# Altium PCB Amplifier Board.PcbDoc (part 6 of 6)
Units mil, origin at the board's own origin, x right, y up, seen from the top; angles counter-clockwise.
Board outline 6000 x 2640 mil, 6 copper layers (Top Layer, GND, VCC, BASES, GND (Plane3), Bottom Layer), stack 63.9 mil thick; 884 components, 484 nets, 2029 pads, 464 vias.
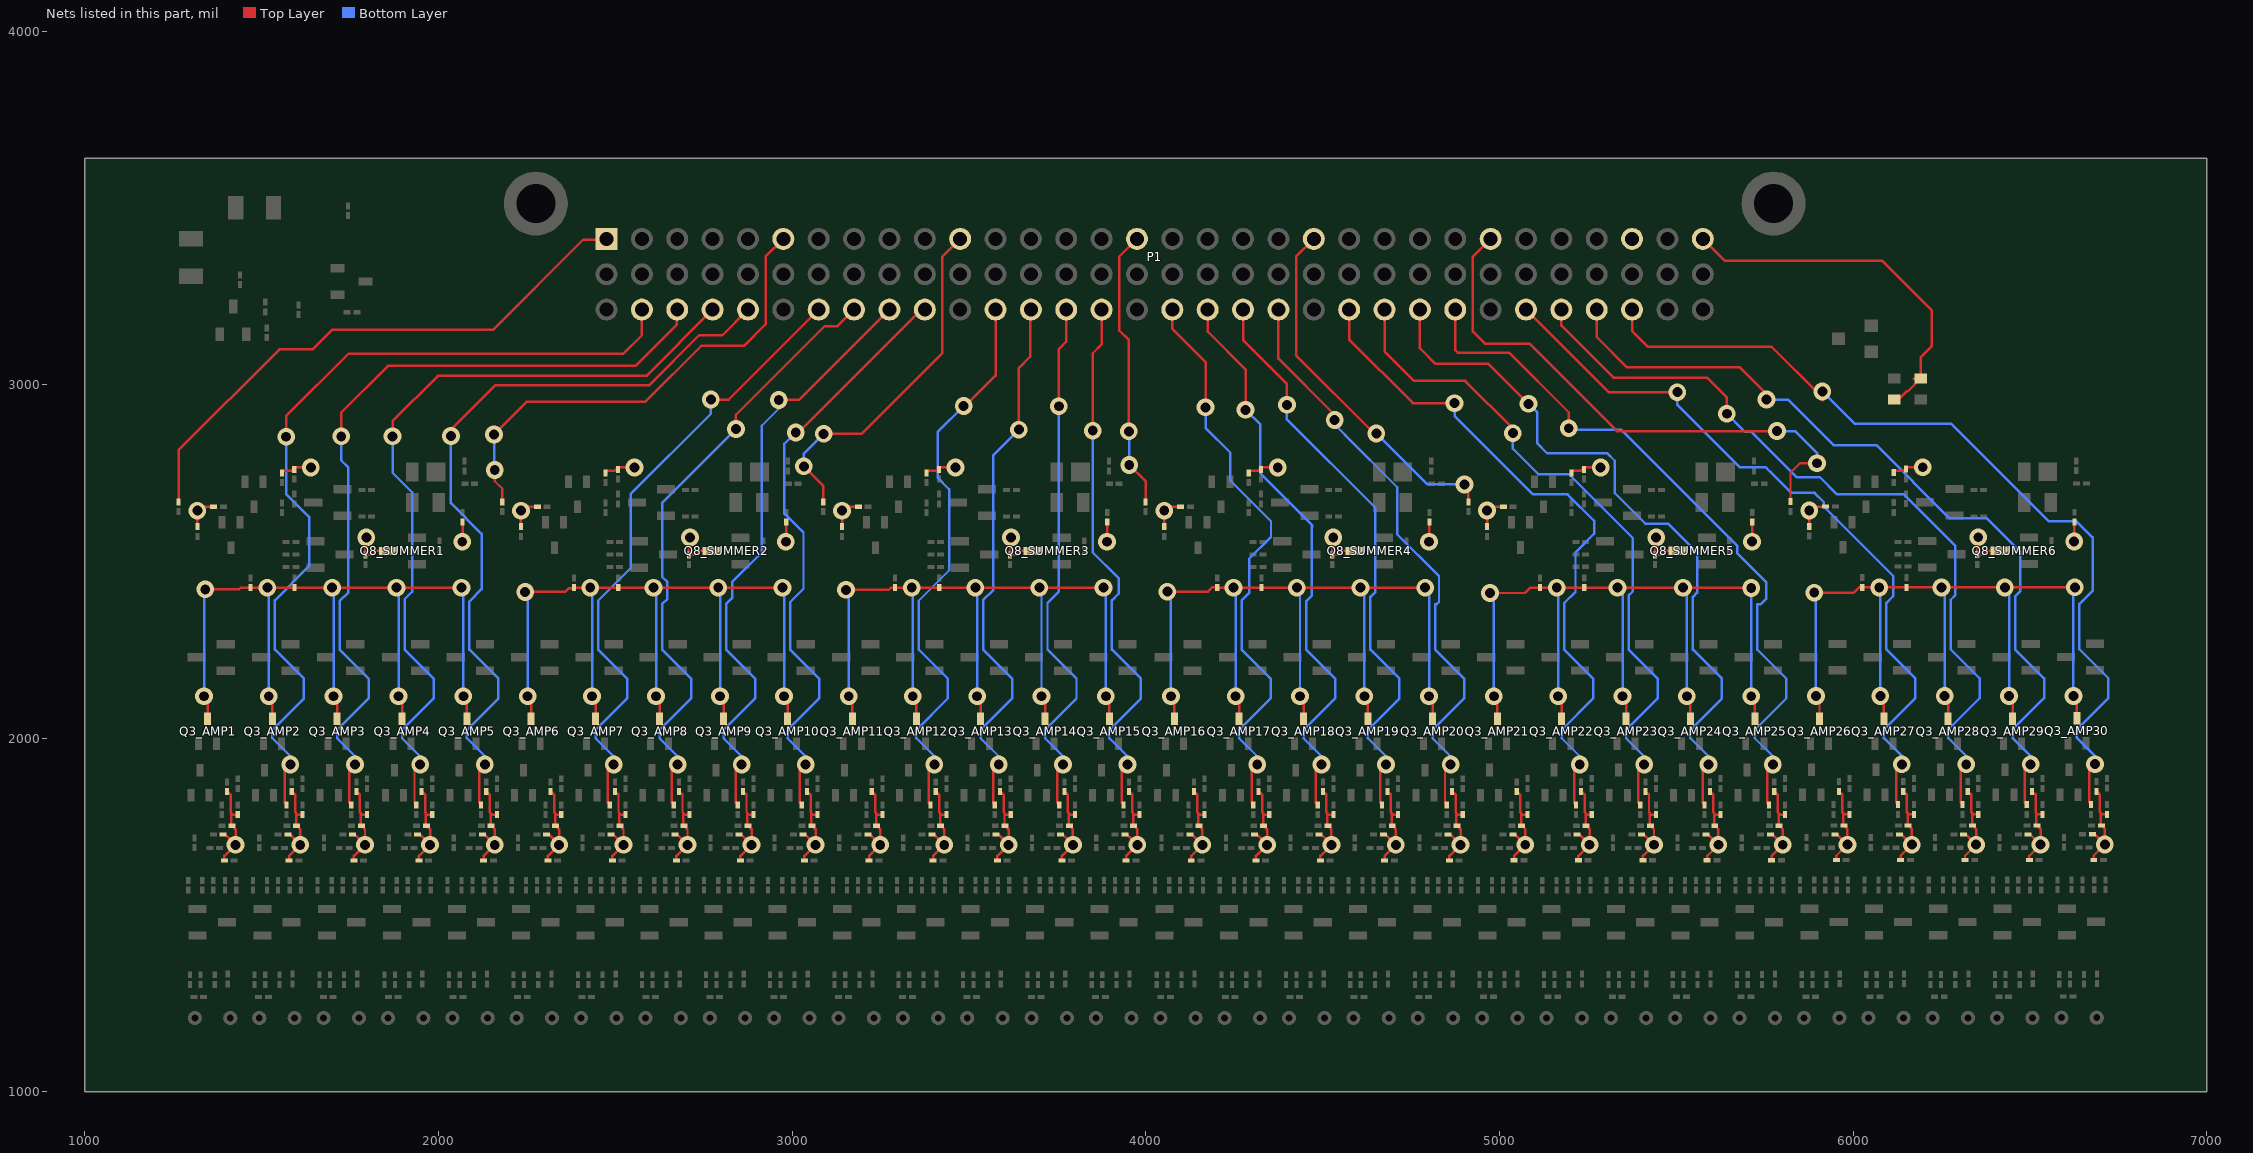
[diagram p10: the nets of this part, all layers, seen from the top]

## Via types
v1: diameter 50, hole 28, Top Layer to Bottom Layer, 433 vias
v2: diameter 50, hole 28, Top Layer to Bottom Layer, tented top, 31 vias

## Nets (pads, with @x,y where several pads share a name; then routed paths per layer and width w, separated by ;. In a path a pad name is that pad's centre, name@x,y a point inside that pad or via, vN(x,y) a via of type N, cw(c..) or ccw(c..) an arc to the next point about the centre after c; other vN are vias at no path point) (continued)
SIPMOUT2_SUMMER1: C5_AMP2.2 P1.C2 | length 2433.2
  Top Layer w7: C5_AMP2.2@1565.78,1817 1565,1817.78 1565,1910 v1(1581,1926) ; v1(1569,2853) 1569,2911 1746,3088 2523,3088 2575,3140 P1.C2@2575,3212.36
  Bottom Layer w7: v1(1569,2853) 1569,2691 1634,2626 1634,2487.16 1537,2390.16 1537,2251 1619,2169 1619,2113 1530,2024 1530,2000.32 1581,1949.32 v1(1581,1926)
SIPMOUT2_SUMMER2: C5_AMP7.2 P1.C7 | length 1782.4
  Top Layer w7: C5_AMP7.2@2479.78,1817 2479,1817.78 2479,1910 v1(2495,1926) ; v1(2770,2958) 2820.64,2958 P1.C7@3075,3212.36
  Bottom Layer w7: v1(2495,1926) 2495,1949.32 2444,2000.32 2444,2024 2533,2113 2533,2169 2451,2251 2451,2389 2543,2481 2543,2691 2770,2918 v1(2770,2958)
SIPMOUT2_SUMMER3: C5_AMP12.2 P1.C12 | length 1613.8
  Top Layer w7: C5_AMP12.2@3386.78,1817 3386,1817.78 3386,1910 v1(3402,1926) ; v1(3485,2940) 3489,2940 3575,3026 P1.C12@3575,3212.36
  Bottom Layer w7: v1(3402,1926) 3402,1949.32 3351,2000.32 3351,2024 3440,2113 3440,2169 3358,2251 3358,2389.22 3444,2475.22 3444,2704.16 3411,2737.16 3411,2866 v1(3485,2940)
SIPMOUT2_SUMMER4: C5_AMP17.2 P1.C17 | length 1644.2
  Top Layer w7: P1.C17@4075,3212.36 4075,3158 4169,3064 v1(4169,2936) ; C5_AMP17.2@4299.78,1817 4299,1817.78 4299,1910 v1(4315,1926)
  Bottom Layer w7: v1(4169,2936) 4169,2878 4238.84,2808.16 4238.84,2729 4354,2613.84 4354,2569.77 4292,2507.77 4292,2410.5 4271,2389.5 4271,2251 4353,2169 4353,2113 4264,2024 4264,2000.32 4315,1949.32 v1(4315,1926)
SIPMOUT2_SUMMER5: C5_AMP22.2 P1.C22 | length 1943
  Top Layer w7: P1.C22@4575,3212.36 4575,3128 4755,2948 v1(4873,2948) ; C5_AMP22.2@5211.78,1817.1 5211,1817.88 5211,1910.1 v1(5227,1926.1)
  Bottom Layer w7: v1(4873,2948) 4873,2911.7 5094.6,2690.1 5192.74,2690.1 5268,2614.84 5268,2579 5215,2526 5215,2414 5183,2382 5183,2251.1 5265,2169.1 5265,2113.1 5176,2024.1 5176,2000.42 5227,1949.42 v1(5227,1926.1)
SIPMOUT2_SUMMER6: C5_AMP27.2 P1.C27 | length 2125.1
  Top Layer w7: P1.C27@5075,3212.36 5308.36,2979 v1(5503,2979) ; C5_AMP27.2@6122.78,1817.57 6122,1818.35 6122,1910.57 v1(6138,1926.57)
  Bottom Layer w7: v1(5503,2979) 5503,2943 5679,2767 5752,2767 5765.59,2753.41 5766.59,2753.41 5823,2697 ; 5824,2694 5891,2694 5917,2668 5917,2655.57 6113.44,2459.13 6113.44,2402.44 6094,2383 6094,2251.57 6176,2169.57 6176,2113.57 6087,2024.57 6087,2000.89 6138,1949.89 v1(6138,1926.57)
SIPMOUT3_SUMMER1: C5_AMP3.2 P1.C3 | length 2313.6
  Top Layer w7: v1(1725,2854) 1725,2921 1857,3053 2557,3053 2673,3169 P1.C3@2673,3210.36 ; C5_AMP3.2@1748.78,1817 1748,1817.78 1748,1910 v1(1764,1926)
  Bottom Layer w7: v1(1725,2854) 1725,2786 1745,2766 1745,2413 1720,2388 1720,2251 1802,2169 1802,2113 1713,2024 1713,2000.32 1764,1949.32 v1(1764,1926)
SIPMOUT3_SUMMER2: C5_AMP8.2 P1.C8 | length 1753.1
  Top Layer w7: C5_AMP8.2@2660.78,1817 2660,1817.78 2660,1910 v1(2676,1926) ; v1(2841,2875) 2841,2915 3092,3166 3128.64,3166 P1.C8@3175,3212.36
  Bottom Layer w7: v1(2676,1926) 2676,1949.32 2625,2000.32 2625,2024 2714,2113 2714,2169 2632,2251 2632,2379.43 2647,2394.43 2647,2442 2632,2457 2632,2666 v1(2841,2875)
SIPMOUT3_SUMMER3: C5_AMP13.2 P1.C13 | length 1547.4
  Top Layer w7: C5_AMP13.2@3568.78,1817 3568,1817.78 3568,1910 v1(3584,1926) ; v1(3641,2873) 3641,3047 3673,3079 P1.C13@3673,3210.36
  Bottom Layer w7: v1(3584,1926) 3584,1949.32 3533,2000.32 3533,2024 3622,2113 3622,2169 3540,2251 3540,2391 3569,2420 3569,2801 v1(3641,2873)
SIPMOUT3_SUMMER4: C5_AMP18.2 P1.C18 | length 1624.3
  Top Layer w7: P1.C18@4175,3212.36 4175,3150 4282,3043 v1(4282,2929) ; C5_AMP18.2@4481.78,1817 4481,1817.78 4481,1910 v1(4497,1926)
  Bottom Layer w7: v1(4282,2929) 4324,2887 4324,2749.23 4470,2603.23 4470,2598.1 ; 4469,2599.32 4469,2403 4453,2387 4453,2251 4535,2169 4535,2113 4446,2024 4446,2000.32 4497,1949.32 v1(4497,1926)
SIPMOUT3_SUMMER5: C5_AMP23.2 P1.C23 | length 1925.2
  Top Layer w7: P1.C23@4675,3212.36 4675,3094 4758,3011 4903,3011 5038,2876 v1(5038,2863) ; C5_AMP23.2@5393.78,1817.1 5393,1817.88 5393,1910.1 v1(5409,1926.1)
  Bottom Layer w7: v1(5038,2863) 5038,2819 5109.81,2747.19 5195.81,2747.19 5377,2566 5377,2415.49 5365,2403.49 5365,2251.1 5447,2169.1 5447,2113.1 5358,2024.1 5358,2000.42 5409,1949.42 v1(5409,1926.1)
SIPMOUT3_SUMMER6: C5_AMP28.2 P1.C28 | length 2275.4
  Top Layer w7: P1.C28@5175,3212.36 5175,3167 5322,3020 5587,3020 5643,2964 v1(5643,2918) ; C5_AMP28.2@6304.78,1817.57 6304,1818.35 6304,1910.57 v1(6320,1926.57)
  Bottom Layer w7: v1(5643,2918) 5692,2869 5710.4,2869 5840.4,2739 5905.7,2739 5954.73,2689.97 6143.5,2689.97 6289,2544.48 6289,2405 6276,2392 6276,2251.57 6358,2169.57 6358,2113.57 6269,2024.57 6269,2000.89 6320,1949.89 v1(6320,1926.57)
SIPMOUT4_SUMMER1: C5_AMP4.2 P1.C4 | length 2246.5
  Top Layer w7: v1(1870,2854) 1870,2897 1998,3025 2587.64,3025 P1.C4@2775,3212.36 ; C5_AMP4.2@1932.78,1817 1932,1817.78 1932,1910 v1(1948,1926)
  Bottom Layer w7: v1(1870,2854) 1870,2751 1925.56,2695.44 1925.56,2414.78 1904,2393.22 1904,2251 1986,2169 1986,2113 1897,2024 1897,2000.32 1948,1949.32 v1(1948,1926)
SIPMOUT4_SUMMER2: C5_AMP9.2 P1.C9 | length 1719.4
  Top Layer w7: C5_AMP9.2@2841.78,1817 2841,1817.78 2841,1910 v1(2857,1926) ; v1(2962,2957) 3019.64,2957 P1.C9@3275,3212.36
  Bottom Layer w7: v1(2857,1926) 2857,1949.32 2806,2000.32 2806,2024 2895,2113 2895,2169 2813,2251 2813,2379.43 2830,2396.43 2830,2442 2914,2526 2914,2884 2962,2932 v1(2962,2957)
SIPMOUT4_SUMMER3: C5_AMP14.2 P1.C14 | length 1516.2
  Top Layer w7: C5_AMP14.2@3750.78,1817 3750,1817.78 3750,1910 v1(3766,1926) ; v1(3754,2939) 3754,3101 3775,3122 P1.C14@3775,3212.36
  Bottom Layer w7: v1(3754,2939) 3754,2415 3722,2383 3722,2251 3804,2169 3804,2113 3715,2024 3715,2000.32 3766,1949.32 v1(3766,1926)
SIPMOUT4_SUMMER4: C5_AMP19.2 P1.C19 | length 1655
  Top Layer w7: P1.C19@4275,3212.36 4275,3126 4399,3002 v1(4399,2943) ; C5_AMP19.2@4663.78,1817 4663,1817.78 4663,1910 v1(4679,1926)
  Bottom Layer w7: v1(4399,2943) 4399,2902 4649,2652 4649,2413.8 4635,2399.8 4635,2251 4717,2169 4717,2113 4628,2024 4628,2000.32 4679,1949.32 v1(4679,1926)
SIPMOUT4_SUMMER5: C5_AMP24.2 P1.C24 | length 2049.2
  Top Layer w7: P1.C24@4775,3212.36 4775,3103 4819,3059 4969,3059 v1(5082,2946) ; C5_AMP24.2@5575.78,1817.1 5575,1817.88 5575,1910.1 v1(5591,1926.1)
  Bottom Layer w7: v1(5082,2946) 5107,2921 5107,2834 5135,2806 5305,2806 5326,2785 5326,2693.44 5412.34,2607.1 5477,2607.1 5559,2525.1 5559,2411.9 5547,2399.9 5547,2251.1 5629,2169.1 5629,2113.1 5540,2024.1 5540,2000.42 5591,1949.42 v1(5591,1926.1)
SIPMOUT4_SUMMER6: C5_AMP29.2 P1.C29 | length 2351.3
  Top Layer w7: P1.C29@5275,3212.36 5275,3135 5361,3049 5680,3049 5755,2974 v1(5755,2958) ; C5_AMP29.2@6486.78,1817.57 6486,1818.35 6486,1910.57 v1(6502,1926.57)
  Bottom Layer w7: v1(5755,2958) 5816,2958 5945,2829 6065.7,2829 6272.7,2622 6378.29,2622 6473,2527.29 6473,2416.47 6458,2401.47 6458,2251.57 6540,2169.57 6540,2113.57 6451,2024.57 6451,2000.89 6502,1949.89 v1(6502,1926.57)
SIPMOUT5_SUMMER1: C5_AMP5.2 P1.C5 | length 2186
  Top Layer w7: v1(2035,2855) 2035,2873 2160,2998 2595,2998 2737,3140 2802.64,3140 P1.C5@2875,3212.36 ; C5_AMP5.2@2115.78,1817 2115,1817.78 2115,1910 v1(2131,1926)
  Bottom Layer w7: v1(2035,2855) 2035,2665 2122,2578 2122,2422 2087,2387 2087,2251 2169,2169 2169,2113 2080,2024 2080,2000.32 2131,1949.32 v1(2131,1926)
SIPMOUT5_SUMMER2: C5_AMP10.2 P1.C10 | length 1697.4
  Top Layer w7: v1(3010,2865) 3018,2865 P1.C10@3365.36,3212.36 ; C5_AMP10.2@3022.78,1817 3022,1817.78 3022,1910 v1(3038,1926)
  Bottom Layer w7: v1(3010,2865) 2978.16,2833.16 2978.16,2635.75 3032,2581.91 3032,2423 2994,2385 2994,2251 3076,2169 3076,2113 2987,2024 2987,2000.32 3038,1949.32 v1(3038,1926)
SIPMOUT5_SUMMER3: C5_AMP15.2 P1.C15 | length 1542.7
  Top Layer w7: v1@3850,2873 3850,3089 3875,3114 P1.C15@3875,3212.36 ; C5_AMP15.2@3932.78,1817 3932,1817.78 3932,1910 v1(3948,1926)
  Bottom Layer w7: v1@3850,2873 v1(3850,2870) 3850,2526 3923,2453 3923,2409 3904,2390 3904,2251 3986,2169 3986,2113 3897,2024 3897,2000.32 3948,1949.32 v1(3948,1926)
SIPMOUT5_SUMMER4: C5_AMP20.2 P1.C20 | length 1686
  Top Layer w7: P1.C20@4375,3212.36 4375,3074 4534,2915 v1(4534,2900) ; C5_AMP20.2@4846.78,1817 4846,1817.78 4846,1910 v1(4862,1926)
  Bottom Layer w7: v1@4528,2894 4562,2860 4562,2859 4711,2710 4711,2576.91 4829,2458.91 4829,2386 4822.43,2379.43 4818,2379.43 4818,2251 4900,2169 4900,2113 4811,2024 4811,2000.32 4862,1949.32 v1(4862,1926)
SIPMOUT5_SUMMER5: C5_AMP25.2 P1.C25 | length 2044.9
  Top Layer w7: P1.C25@4875,3212.36 4875,3098 4882,3091 5027,3091 5196,2922 v1(5196,2877) ; C5_AMP25.2@5757.78,1817.1 5757,1817.88 5757,1910.1 v1(5773,1926.1)
  Bottom Layer w7: v1(5196,2877) 5201,2872 5345,2872 5672,2545 5672,2524 5755,2441 5755,2395 5739.53,2379.53 5729,2379.53 5729,2251.1 5811,2169.1 5811,2113.1 5722,2024.1 5722,2000.42 5773,1949.42 v1(5773,1926.1)
SIPMOUT5_SUMMER6: C5_AMP30.2 P1.C30 | length 2484.4
  Top Layer w7: P1.C30@5375,3212.36 5375,3152 5420,3107 5770,3107 5904.5,2972.5 5914,2963 5914,2956 ; C5_AMP30.2@6668.78,1818 6668,1818.78 6668,1911 v1(6684,1927)
  Bottom Layer w7: v1(5913,2981) 6005,2889 6278,2889 6553.43,2613.57 6631.5,2613.57 6677,2568.07 6677,2417 6640,2380 ; 6640,2380.43 6640,2380 ; v1(6684,1927) 6684,1950.32 6633,2001.32 6633,2025 6722,2114 6722,2170 6640,2252 6640,2380
SUMMEDOUT1: C9_SUMMER1.2 P1.A1 | length 1603.7
  Top Layer w7: C9_SUMMER1.2@1265,2668.78 1265,2815 1550,3100 1644,3100 1699,3155 2154,3155 2409,3410 2472.64,3410 P1.A1@2475,3412.36
SUMMEDOUT2: C9_SUMMER2.2 P1.A6 | length 1356.2
  Top Layer w7: v1(2157,2859) 2250,2952 2585,2952 2743,3110 2864,3110 2925,3171 2925,3362.36 P1.A6@2975,3412.36 ; v1(2159,2759) 2159,2727 2180,2706 C9_SUMMER2.2@2180,2668.78
  Bottom Layer w7: v1@2157,2761 v1(2157,2859)
SUMMEDOUT3: C9_SUMMER3.2 P1.A11 | length 1012.1
  Top Layer w7: v1(3033,2769) 3088,2714 C9_SUMMER3.2@3088,2668.78 ; v1(3089,2861) 3196,2861 3425,3090 3425,3362.36 P1.A11@3475,3412.36
  Bottom Layer w7: v1(3033,2769) 3033,2805 v1(3089,2861)
SUMMEDOUT4: C9_SUMMER4.2 P1.A16 | length 790.7
  Top Layer w7: v1(3952,2868) 3952,3126 3925,3153 3925,3362.36 P1.A16@3975,3412.36 ; v1(3953,2773) 4000,2726 C9_SUMMER4.2@4000,2672
  Bottom Layer w7: v1(3953,2773) v1@3953,2867
SUMMEDOUT5: C9_SUMMER5.2 P1.A21 | length 1059.6
  Top Layer w7: P1.A21@4446.36,3412.36 P1.A21@4475,3412.36 4425,3362.36 4425,3083 4646,2862 v1(4652,2862) ; v1(4901,2718) 4912,2707 C9_SUMMER5.2@4912,2668.88
  Bottom Layer w7: v1(4652,2862) 4796,2718 v1(4901,2718)
SUMMEDOUT6: C9_SUMMER6.2 P1.A26 | length 1595
  Top Layer w7: P1.A26@4975,3412.36 4925,3362.36 4925,3150 4959,3116 5085,3116 5332,2869 v1(5785,2869) ; C9_SUMMER6.2@5823,2669.35 5823,2751 5850,2778 v1(5898,2778)
  Bottom Layer w7: v1(5785,2869) 5836,2869 5898,2807 v1(5898,2778)
THERMAL: P1.A32 R27.1 RT1.1 | length 1057.1
  Top Layer w7: P1.A32@5575,3412.36 5636.36,3351 6082,3351 6223,3210 6223,3109 6191,3077 R27.1@6191,3017.53 ; RT1.1@6116,2958.47 6128.47,2958.47 6151,2981 6154.47,2981 R27.1@6191,3017.53 ; 6170.87,3017.53 R27.1@6191,3017.53
TOSUM_SUMMER1: C7_SUMMER1.1 Q3_AMP1.3 Q3_AMP2.3 Q3_AMP3.3 Q3_AMP4.3 Q3_AMP5.3 R9_SUMMER1.2 | length 2589.7
  Top Layer w7: v1(1337,2119) 1347,2109 Q3_AMP1.3@1347,2055.43 ; v1(1340.31,2421.31) 1435.75,2421.31 1440.66,2426.22 R9_SUMMER1.2@1468,2426.22 v1(1516,2426.22) C7_SUMMER1.1@1593,2426.22 v1(1699,2426.22) v1(1881,2426.22) v1(2065,2426.22) ; v1(1520,2119) 1530,2109 Q3_AMP2.3@1530,2055.43 ; v1(1703,2119) 1713,2109 Q3_AMP3.3@1713,2055.43 ; v1(1887,2119) 1897,2109 Q3_AMP4.3@1897,2055.43 ; v1(2070,2119) 2080,2109 Q3_AMP5.3@2080,2055.43
  Bottom Layer w7: v1(1337,2119) v1@1337,2418 ; v1(1520,2119) v1@1520,2425.22 ; v1(1703,2119) 1703,2426.22 v1@1703,2429 ; v1(1887,2119) v1@1887,2417.22 ; v1(2070,2119) 2070,2426.22 v1@2070,2430
TOSUM_SUMMER2: C7_SUMMER2.1 Q3_AMP6.3 Q3_AMP7.3 Q3_AMP8.3 Q3_AMP9.3 Q3_AMP10.3 R9_SUMMER2.2 | length 2566
  Top Layer w7: v1(2245,2414) 2358,2414 2369,2425 2383,2425 2383.16,2425 2383.69,2425.53 2384.38,2426.22 v1(2429,2426.22) C7_SUMMER2.1@2508,2426.22 v1(2608,2426.22) v1(2791,2426.22) v1(2972.78,2426.22) ; v1(2252,2119) 2262,2109 Q3_AMP6.3@2262,2055.43 ; v1(2434,2119) 2444,2109 Q3_AMP7.3@2444,2055.43 ; v1(2615,2119) 2625,2109 Q3_AMP8.3@2625,2055.43 ; v1(2796,2119) 2806,2109 Q3_AMP9.3@2806,2055.43 ; v1(2977,2119) 2987,2109 Q3_AMP10.3@2987,2055.43
  Bottom Layer w7: v1(2252,2119) v1@2252,2407 ; v1(2434,2119) v1@2434,2423.22 ; v1(2615,2119) v1@2615,2417.22 ; v1(2796,2119) v1@2796,2420.22 ; v1(2977,2119) v1@2977,2422
TOSUM_SUMMER3: C7_SUMMER3.1 Q3_AMP11.3 Q3_AMP12.3 Q3_AMP13.3 Q3_AMP14.3 Q3_AMP15.3 R9_SUMMER3.2 | length 2565.4
  Top Layer w7: v1(3152,2420) 3273,2420 3279.22,2426.22 R9_SUMMER3.2@3291,2426.22 v1(3338,2426.22) C7_SUMMER3.1@3416,2426.22 v1(3518,2426.22) v1(3699,2426.22) v1(3880.22,2426.22) ; v1(3160,2119) 3170,2109 Q3_AMP11.3@3170,2055.43 ; v1(3341,2119) 3351,2109 Q3_AMP12.3@3351,2055.43 ; v1(3523,2119) 3533,2109 Q3_AMP13.3@3533,2055.43 ; v1(3705,2119) 3715,2109 Q3_AMP14.3@3715,2055.43 ; v1(3887,2119) 3897,2109 Q3_AMP15.3@3897,2055.43
  Bottom Layer w7: v1(3160,2119) v1@3160,2412 ; v1(3341,2119) v1@3341,2424.22 ; v1(3523,2119) v1@3523,2417.22 ; v1(3705,2119) v1@3705,2418.22 ; v1(3887,2119) v1@3887,2419.44
TOSUM_SUMMER4: C7_SUMMER4.1 Q3_AMP16.3 Q3_AMP17.3 Q3_AMP18.3 Q3_AMP19.3 Q3_AMP20.3 R9_SUMMER4.2 | length 2602.8
  Top Layer w7: v1(4061,2415) 4176,2415 4188.6,2427.6 R9_SUMMER4.2@4202,2427.6 ; v1(4071,2119) 4081,2109 Q3_AMP16.3@4081,2055.43 ; R9_SUMMER4.2@4202,2426.22 v1(4248,2426.22) C7_SUMMER4.1@4327,2426.22 v1(4427,2426.22) v1(4607,2426.22) v1(4789.78,2426.22) ; v1(4254,2119) 4264,2109 Q3_AMP17.3@4264,2055.43 ; v1(4436,2119) 4446,2109 Q3_AMP18.3@4446,2055.43 ; v1(4618,2119) 4628,2109 Q3_AMP19.3@4628,2055.43 ; v1(4801,2119) 4811,2109 Q3_AMP20.3@4811,2055.43
  Bottom Layer w7: v1(4061,2415) 4071,2405 v1(4071,2119) ; v1@4249,2426.22 4254,2421.22 v1(4254,2119) ; v1@4424,2426.22 4425.5,2424.72 4436,2414.22 v1(4436,2119) ; v1@4605,2426.22 4606,2425.22 4618,2413.22 v1(4618,2119) ; v1(4801,2119) v1@4801,2415
TOSUM_SUMMER5: C7_SUMMER5.1 Q3_AMP21.3 Q3_AMP22.3 Q3_AMP23.3 Q3_AMP24.3 Q3_AMP25.3 R9_SUMMER5.2 | length 2630.6
  Top Layer w7: v1(4973,2411) 5072.34,2411 5087.66,2426.32 R9_SUMMER5.2@5115,2426.32 v1(5162,2426.32) C7_SUMMER5.1@5240,2426.32 v1(5334,2426.32) v1(5519,2426.32) 5712,2426.32 v1@5713,2426.32 ; v1(4984,2119.1) 4994,2109.1 Q3_AMP21.3@4994,2055.54 ; v1(5166,2119.1) 5176,2109.1 Q3_AMP22.3@5176,2055.54 ; v1(5348,2119.1) 5358,2109.1 Q3_AMP23.3@5358,2055.54 ; v1(5530,2119.1) 5540,2109.1 Q3_AMP24.3@5540,2055.54 ; v1(5712,2119.1) 5722,2109.1 Q3_AMP25.3@5722,2055.54
  Bottom Layer w7: v1(4973,2411) 4984,2400 v1(4984,2119.1) ; v1@5160,2425.32 5160.5,2424.82 5166,2419.32 v1(5166,2119.1) ; v1@5333,2435 5337.84,2430.16 5348,2420 v1(5348,2119.1) ; v1@5518,2426.32 5518.5,2425.82 5530,2414.32 v1(5530,2119.1) ; v1(5712,2119.1) v1(5712,2425.32)
TOSUM_SUMMER6: C7_SUMMER6.1 Q3_AMP26.3 Q3_AMP27.3 Q3_AMP28.3 Q3_AMP29.3 Q3_AMP30.3 R9_SUMMER6.2 | length 2591.6
  Top Layer w7: v1(5890,2412) 6002,2412 6016.79,2426.79 R9_SUMMER6.2@6026,2426.79 v1(6074,2426.79) C7_SUMMER6.1@6151,2426.79 v1(6250,2426.79) v1(6429,2426.79) v1@6627,2426.79 ; v1(5895,2119.57) 5905,2109.57 Q3_AMP26.3@5905,2056 ; v1(6077,2119.57) 6087,2109.57 Q3_AMP27.3@6087,2056 ; v1(6259,2119.57) 6269,2109.57 Q3_AMP28.3@6269,2056 ; v1(6441,2119.57) 6451,2109.57 Q3_AMP29.3@6451,2056 ; v1(6623,2120) 6633,2110 Q3_AMP30.3@6633,2056.43
  Bottom Layer w7: v1(5890,2412) 5895,2407 v1(5895,2119.57) ; v1(6074,2426.79) 6077,2423.79 v1(6077,2119.57) ; v1@6253,2426.79 6259,2420.79 v1(6259,2119.57) ; v1(6441,2119.57) v1@6441,2413.79 ; v1(6623,2120) v1@6623,2423
  other v1: 6627,2427
VCC: P1.A30 Q8_SUMMER1.3 Q8_SUMMER2.3 Q8_SUMMER3.3 Q8_SUMMER4.3 Q8_SUMMER5.3 Q8_SUMMER6.3 R4_AMP1.2 R4_AMP2.2 R4_AMP3.2 R4_AMP4.2 R4_AMP5.2 R4_AMP6.2 R4_AMP7.2 R4_AMP8.2 R4_AMP9.2 R4_AMP10.2 R4_AMP11.2 R4_AMP12.2 R4_AMP13.2 R4_AMP14.2 R4_AMP15.2 R4_AMP16.2 R4_AMP17.2 R4_AMP18.2 R4_AMP19.2 R4_AMP20.2 R4_AMP21.2 R4_AMP22.2 R4_AMP23.2 R4_AMP24.2 R4_AMP25.2 R4_AMP26.2 R4_AMP27.2 R4_AMP28.2 R4_AMP29.2 R4_AMP30.2 R5_AMP1.2 R5_AMP2.2 R5_AMP3.2 R5_AMP4.2 R5_AMP5.2 R5_AMP6.2 R5_AMP7.2 R5_AMP8.2 R5_AMP9.2 R5_AMP10.2 R5_AMP11.2 R5_AMP12.2 R5_AMP13.2 R5_AMP14.2 R5_AMP15.2 R5_AMP16.2 R5_AMP17.2 R5_AMP18.2 R5_AMP19.2 R5_AMP20.2 R5_AMP21.2 R5_AMP22.2 R5_AMP23.2 R5_AMP24.2 R5_AMP25.2 R5_AMP26.2 R5_AMP27.2 R5_AMP28.2 R5_AMP29.2 R5_AMP30.2 R7_AMP1.2 R7_AMP2.2 R7_AMP3.2 R7_AMP4.2 R7_AMP5.2 R7_AMP6.2 R7_AMP7.2 R7_AMP8.2 R7_AMP9.2 R7_AMP10.2 R7_AMP11.2 R7_AMP12.2 R7_AMP13.2 R7_AMP14.2 R7_AMP15.2 R7_AMP16.2 R7_AMP17.2 R7_AMP18.2 R7_AMP19.2 R7_AMP20.2 R7_AMP21.2 R7_AMP22.2 R7_AMP23.2 R7_AMP24.2 R7_AMP25.2 R7_AMP26.2 R7_AMP27.2 R7_AMP28.2 R7_AMP29.2 R7_AMP30.2 R8_AMP1.2 R8_AMP2.2 R8_AMP3.2 R8_AMP4.2 R8_AMP5.2 R8_AMP6.2 R8_AMP7.2 R8_AMP8.2 R8_AMP9.2 R8_AMP10.2 R8_AMP11.2 R8_AMP12.2 R8_AMP13.2 R8_AMP14.2 R8_AMP15.2 R8_AMP16.2 R8_AMP17.2 R8_AMP18.2 R8_AMP19.2 R8_AMP20.2 R8_AMP21.2 R8_AMP22.2 R8_AMP23.2 R8_AMP24.2 R8_AMP25.2 R8_AMP26.2 R8_AMP27.2 R8_AMP28.2 R8_AMP29.2 R8_AMP30.2 R10_SUMMER1.2 R10_SUMMER2.2 R10_SUMMER3.2 R10_SUMMER4.2 R10_SUMMER5.2 R10_SUMMER6.2 R11_SUMMER1.2 R11_SUMMER2.2 R11_SUMMER3.2 R11_SUMMER4.2 R11_SUMMER5.2 R11_SUMMER6.2 R13_SUMMER1.2 R13_SUMMER2.2 R13_SUMMER3.2 R13_SUMMER4.2 R13_SUMMER5.2 R13_SUMMER6.2 R15_SUMMER1.2 R15_SUMMER2.2 R15_SUMMER3.2 R15_SUMMER4.2 R15_SUMMER5.2 R15_SUMMER6.2 R16_SUMMER1.2 R16_SUMMER2.2 R16_SUMMER3.2 R16_SUMMER4.2 R16_SUMMER5.2 R16_SUMMER6.2 R20_AMP1.2 R20_AMP2.2 R20_AMP3.2 R20_AMP4.2 R20_AMP5.2 R20_AMP6.2 R20_AMP7.2 R20_AMP8.2 R20_AMP9.2 R20_AMP10.2 R20_AMP11.2 R20_AMP12.2 R20_AMP13.2 R20_AMP14.2 R20_AMP15.2 R20_AMP16.2 R20_AMP17.2 R20_AMP18.2 R20_AMP19.2 R20_AMP20.2 R20_AMP21.2 R20_AMP22.2 R20_AMP23.2 R20_AMP24.2 R20_AMP25.2 R20_AMP26.2 R20_AMP27.2 R20_AMP28.2 R20_AMP29.2 R20_AMP30.2 RD_SUMMER1.2 RD_SUMMER2.2 RD_SUMMER3.2 RD_SUMMER4.2 RD_SUMMER5.2 RD_SUMMER6.2 | length 11148.3
  Top Layer w7: R16_SUMMER1.2@1318,2598.78 v1(1318,2644) 1329,2655 R15_SUMMER1.2@1364.22,2655 ; R4_AMP1.2@1390.78,1728 1397,1728 v1(1426,1699) ; R20_AMP1.2@1394.44,1655 1394.44,1667.44 v1(1426,1699) ; R5_AMP1.2@1414.4,1753 1414.4,1784.22 ; R5_AMP1.2@1415.78,1753 1426,1742.78 v1(1426,1699) ; R7_AMP1.2@1432,1784.22 1414.4,1784.22 ; RD_SUMMER1.2@1557,2750.78 1562.78,2756.56 1582.67,2756.56 1589.44,2763.34 1592.1,2766 v1(1639,2766) ; R4_AMP2.2@1573.78,1728 1580,1728 v1(1609,1699) ; R20_AMP2.2@1577.44,1655 1577.44,1667.44 v1(1609,1699) ; R5_AMP2.2@1597.4,1753 1597.4,1784.22 ; R5_AMP2.2@1598.78,1753 1609,1742.78 v1(1609,1699) ; R7_AMP2.2@1615,1784.22 1597.4,1784.22 ; R4_AMP3.2@1756.78,1728 1763,1728 v1(1792,1699) ; R20_AMP3.2@1760.44,1655 1760.44,1667.44 v1(1792,1699) ; R5_AMP3.2@1780.4,1753 1780.4,1784.22 ; R5_AMP3.2@1781.78,1753 1792,1742.78 v1(1792,1699) ; v1@1793,2565 R11_SUMMER1.2@1793,2518.78 1811.01,2518.78 1822.23,2530 Q8_SUMMER1.3@1856.66,2530 ; R7_AMP3.2@1798,1784.22 1780.4,1784.22 ; R4_AMP4.2@1940.78,1728 1947,1728 v1(1976,1699) ; R20_AMP4.2@1944.44,1655 1944.44,1667.44 v1(1976,1699) ; R5_AMP4.2@1964.4,1753 1964.4,1784.22 ; R5_AMP4.2@1965.78,1753 1976,1742.78 v1(1976,1699) ; R7_AMP4.2@1982,1784.22 1964.4,1784.22 ; v1@2068,2557 R10_SUMMER1.2@2068,2611.22 ; R4_AMP5.2@2123.78,1728 2130,1728 v1(2159,1699) ; R20_AMP5.2@2127.44,1655 2127.44,1667.44 v1(2159,1699) ; R5_AMP5.2@2147.4,1753 2147.4,1784.22 ; R5_AMP5.2@2148.78,1753 2159,1742.78 v1(2159,1699) ; R7_AMP5.2@2165,1784.22 2147.4,1784.22 ; R16_SUMMER2.2@2233,2598.78 v1(2233,2644) 2244,2655 R15_SUMMER2.2@2279.22,2655 ; R4_AMP6.2@2305.78,1728 2312,1728 v1(2341,1699) ; R20_AMP6.2@2309.44,1655 2309.44,1667.44 v1(2341,1699) ; R5_AMP6.2@2329.4,1753 2329.4,1784.22 ; R5_AMP6.2@2330.78,1753 2341,1742.78 v1(2341,1699) ; R7_AMP6.2@2347,1784.22 2329.4,1784.22 ; RD_SUMMER2.2@2472,2750.78 2477.78,2756.56 2497.67,2756.56 2504.44,2763.34 2507.1,2766 v1(2554,2766) ; R4_AMP7.2@2487.78,1728 2494,1728 v1(2523,1699) ; R20_AMP7.2@2491.44,1655 2491.44,1667.44 v1(2523,1699) ; R5_AMP7.2@2511.4,1753 2511.4,1784.22 ; R5_AMP7.2@2512.78,1753 2523,1742.78 v1(2523,1699) ; R7_AMP7.2@2529,1784.22 2511.4,1784.22 ; R4_AMP8.2@2668.78,1728 2675,1728 v1(2704,1699) ; R20_AMP8.2@2672.44,1655 2672.44,1667.44 v1(2704,1699) ; R5_AMP8.2@2692.4,1753 2692.4,1784.22 ; R5_AMP8.2@2693.78,1753 2704,1742.78 v1(2704,1699) ; v1@2708,2565 R11_SUMMER2.2@2708,2518.78 2726.01,2518.78 2737.23,2530 Q8_SUMMER2.3@2771.66,2530 ; R7_AMP8.2@2710,1784.22 2692.4,1784.22 ; R4_AMP9.2@2849.78,1728 2856,1728 v1(2885,1699) ; R20_AMP9.2@2853.44,1655 2853.44,1667.44 v1(2885,1699) ; R5_AMP9.2@2873.4,1753 2873.4,1784.22 ; R5_AMP9.2@2874.78,1753 2885,1742.78 v1(2885,1699) ; R7_AMP9.2@2891,1784.22 2873.4,1784.22 ; v1@2983,2557 R10_SUMMER2.2@2983,2611.22 ; R4_AMP10.2@3030.78,1728 3037,1728 v1(3066,1699) ; R20_AMP10.2@3034.44,1655 3034.44,1667.44 v1(3066,1699) ; R5_AMP10.2@3054.4,1753 3054.4,1784.22 ; R5_AMP10.2@3055.78,1753 3066,1742.78 v1(3066,1699) ; R7_AMP10.2@3072,1784.22 3054.4,1784.22 ; R16_SUMMER3.2@3141,2598.78 v1(3141,2644) 3152,2655 R15_SUMMER3.2@3187.22,2655 ; R4_AMP11.2@3213.78,1728 3220,1728 v1(3249,1699) ; R20_AMP11.2@3217.44,1655 3217.44,1667.44 v1(3249,1699) ; R5_AMP11.2@3237.4,1753 3237.4,1784.22 ; R5_AMP11.2@3238.78,1753 3249,1742.78 v1(3249,1699) ; R7_AMP11.2@3255,1784.22 3237.4,1784.22 ; RD_SUMMER3.2@3380,2750.78 3385.78,2756.56 3405.67,2756.56 3412.44,2763.34 3415.1,2766 v1(3462,2766) ; R4_AMP12.2@3394.78,1728 3401,1728 v1(3430,1699) ; R20_AMP12.2@3398.44,1655 3398.44,1667.44 v1(3430,1699) ; R5_AMP12.2@3418.4,1753 3418.4,1784.22 ; R5_AMP12.2@3419.78,1753 3430,1742.78 v1(3430,1699) ; R7_AMP12.2@3436,1784.22 3418.4,1784.22 ; R4_AMP13.2@3576.78,1728 3583,1728 v1(3612,1699) ; R20_AMP13.2@3580.44,1655 3580.44,1667.44 v1(3612,1699) ; R5_AMP13.2@3600.4,1753 3600.4,1784.22 ; R5_AMP13.2@3601.78,1753 3612,1742.78 v1(3612,1699) ; v1@3616,2565 R11_SUMMER3.2@3616,2518.78 3634.01,2518.78 3645.23,2530 Q8_SUMMER3.3@3679.66,2530 ; R7_AMP13.2@3618,1784.22 3600.4,1784.22 ; R4_AMP14.2@3758.78,1728 3765,1728 v1(3794,1699) ; R20_AMP14.2@3762.44,1655 3762.44,1667.44 v1(3794,1699) ; R5_AMP14.2@3782.4,1753 3782.4,1784.22 ; R5_AMP14.2@3783.78,1753 3794,1742.78 v1(3794,1699) ; R7_AMP14.2@3800,1784.22 3782.4,1784.22 ; v1@3891,2557 R10_SUMMER3.2@3891,2611.22 ; R4_AMP15.2@3940.78,1728 3947,1728 v1(3976,1699) ; R20_AMP15.2@3944.44,1655 3944.44,1667.44 v1(3976,1699) ; R5_AMP15.2@3964.4,1753 3964.4,1784.22 ; R5_AMP15.2@3965.78,1753 3976,1742.78 v1(3976,1699) ; R7_AMP15.2@3982,1784.22 3964.4,1784.22 ; R16_SUMMER4.2@4052,2598.78 v1(4052,2644) 4063,2655 R15_SUMMER4.2@4098.22,2655 ; R4_AMP16.2@4124.78,1728 4131,1728 v1(4160,1699) ; R20_AMP16.2@4128.44,1655 4128.44,1667.44 v1(4160,1699) ; R5_AMP16.2@4148.4,1753 4148.4,1784.22 ; R5_AMP16.2@4149.78,1753 4160,1742.78 v1(4160,1699) ; R7_AMP16.2@4166,1784.22 4148.4,1784.22 ; RD_SUMMER4.2@4291,2750.78 4296.78,2756.56 4316.67,2756.56 4323.44,2763.34 4326.1,2766 v1(4373,2766) ; R4_AMP17.2@4307.78,1728 4314,1728 v1(4343,1699) ; R20_AMP17.2@4311.44,1655 4311.44,1667.44 v1(4343,1699) ; R5_AMP17.2@4331.4,1753 4331.4,1784.22 ; R5_AMP17.2@4332.78,1753 4343,1742.78 v1(4343,1699) ; R7_AMP17.2@4349,1784.22 4331.4,1784.22 ; R4_AMP18.2@4489.78,1728 4496,1728 v1(4525,1699) ; R20_AMP18.2@4493.44,1655 4493.44,1667.44 v1(4525,1699) ; R5_AMP18.2@4513.4,1753 4513.4,1784.22 ; R5_AMP18.2@4514.78,1753 4525,1742.78 v1(4525,1699) ; v1@4527,2565 R11_SUMMER4.2@4527,2518.78 4545.01,2518.78 4556.23,2530 Q8_SUMMER4.3@4590.66,2530 ; R7_AMP18.2@4531,1784.22 4513.4,1784.22 ; R4_AMP19.2@4671.78,1728 4678,1728 v1(4707,1699) ; R20_AMP19.2@4675.44,1655 4675.44,1667.44 v1(4707,1699) ; R5_AMP19.2@4695.4,1753 4695.4,1784.22 ; R5_AMP19.2@4696.78,1753 4707,1742.78 v1(4707,1699) ; R7_AMP19.2@4713,1784.22 4695.4,1784.22 ; v1@4802,2557 R10_SUMMER4.2@4802,2611.22 ; R4_AMP20.2@4854.78,1728 4861,1728 v1(4890,1699) ; R20_AMP20.2@4858.44,1655 4858.44,1667.44 v1(4890,1699) ; R5_AMP20.2@4878.4,1753 4878.4,1784.22 ; R5_AMP20.2@4879.78,1753 4890,1742.78 v1(4890,1699) ; R7_AMP20.2@4896,1784.22 4878.4,1784.22 ; R16_SUMMER5.2@4965,2598.88 v1(4965,2644.1) 4976,2655.1 R15_SUMMER5.2@5011.22,2655.1 ; R4_AMP21.2@5037.78,1728.1 5044,1728.1 v1(5073,1699.1) ; R20_AMP21.2@5041.44,1655.1 5041.44,1667.54 v1(5073,1699.1) ; R5_AMP21.2@5061.4,1753.1 5061.4,1784.32 ; R5_AMP21.2@5062.78,1753.1 5073,1742.88 v1(5073,1699.1) ; R7_AMP21.2@5079,1784.32 5061.4,1784.32 ; RD_SUMMER5.2@5204,2750.88 5209.78,2756.67 5229.67,2756.67 5236.44,2763.44 5239.1,2766.1 v1(5286,2766.1) ; R4_AMP22.2@5219.78,1728.1 5226,1728.1 v1(5255,1699.1) ; R20_AMP22.2@5223.44,1655.1 5223.44,1667.54 v1(5255,1699.1) ; R5_AMP22.2@5243.4,1753.1 5243.4,1784.32 ; R5_AMP22.2@5244.78,1753.1 5255,1742.88 v1(5255,1699.1) ; R7_AMP22.2@5261,1784.32 5243.4,1784.32 ; R4_AMP23.2@5401.78,1728.1 5408,1728.1 v1(5437,1699.1) ; R20_AMP23.2@5405.44,1655.1 5405.44,1667.54 v1(5437,1699.1) ; R5_AMP23.2@5425.4,1753.1 5425.4,1784.32 ; R5_AMP23.2@5426.78,1753.1 5437,1742.88 v1(5437,1699.1) ; v1@5440,2565.1 R11_SUMMER5.2@5440,2518.88 5458.01,2518.88 5469.23,2530.1 Q8_SUMMER5.3@5503.66,2530.1 ; R7_AMP23.2@5443,1784.32 5425.4,1784.32 ; R4_AMP24.2@5583.78,1728.1 5590,1728.1 v1(5619,1699.1) ; R20_AMP24.2@5587.44,1655.1 5587.44,1667.54 v1(5619,1699.1) ; R5_AMP24.2@5607.4,1753.1 5607.4,1784.32 ; R5_AMP24.2@5608.78,1753.1 5619,1742.88 v1(5619,1699.1) ; R7_AMP24.2@5625,1784.32 5607.4,1784.32 ; v1@5715,2557.1 R10_SUMMER5.2@5715,2611.32 ; R4_AMP25.2@5765.78,1728.1 5772,1728.1 v1(5801,1699.1) ; R20_AMP25.2@5769.44,1655.1 5769.44,1667.54 v1(5801,1699.1) ; R5_AMP25.2@5789.4,1753.1 5789.4,1784.32 ; R5_AMP25.2@5790.78,1753.1 5801,1742.88 v1(5801,1699.1) ; R7_AMP25.2@5807,1784.32 5789.4,1784.32 ; R16_SUMMER6.2@5876,2599.35 v1(5876,2644.57) 5887,2655.57 R15_SUMMER6.2@5922.22,2655.57 ; R4_AMP26.2@5948.78,1728.57 5955,1728.57 v1(5984,1699.57) ; R20_AMP26.2@5952.44,1655.57 5952.44,1668.01 v1(5984,1699.57) ; R5_AMP26.2@5972.4,1753.57 5972.4,1784.79 ; R5_AMP26.2@5973.78,1753.57 5984,1743.35 v1(5984,1699.57) ; R7_AMP26.2@5990,1784.79 5972.4,1784.79 ; RD_SUMMER6.2@6115,2751.35 6120.78,2757.13 6140.67,2757.13 6147.44,2763.91 6150.1,2766.57 v1(6197,2766.57) ; R4_AMP27.2@6130.78,1728.57 6137,1728.57 v1(6166,1699.57) ; R20_AMP27.2@6134.44,1655.57 6134.44,1668.01 v1(6166,1699.57) ; R5_AMP27.2@6154.4,1753.57 6154.4,1784.79 ; R5_AMP27.2@6155.78,1753.57 6166,1743.35 v1(6166,1699.57) ; R7_AMP27.2@6172,1784.79 6154.4,1784.79 ; R4_AMP28.2@6312.78,1728.57 6319,1728.57 v1(6348,1699.57) ; R20_AMP28.2@6316.44,1655.57 6316.44,1668.01 v1(6348,1699.57) ; R5_AMP28.2@6336.4,1753.57 6336.4,1784.79 ; R5_AMP28.2@6337.78,1753.57 6348,1743.35 v1(6348,1699.57) ; v1@6351,2565.57 R11_SUMMER6.2@6351,2519.35 6369.01,2519.35 6380.23,2530.57 Q8_SUMMER6.3@6414.66,2530.57 ; R7_AMP28.2@6354,1784.79 6336.4,1784.79 ; R4_AMP29.2@6494.78,1728.57 6501,1728.57 v1(6530,1699.57) ; R20_AMP29.2@6498.44,1655.57 6498.44,1668.01 v1(6530,1699.57) ; R5_AMP29.2@6518.4,1753.57 6518.4,1784.79 ; R5_AMP29.2@6519.78,1753.57 6530,1743.35 v1(6530,1699.57) ; R7_AMP29.2@6536,1784.79 6518.4,1784.79 ; v1@6626,2557.57 R10_SUMMER6.2@6626,2611.79 ; R4_AMP30.2@6676.78,1729 6683,1729 v1(6712,1700) ; R20_AMP30.2@6680.44,1656 6680.44,1668.44 v1(6712,1700) ; R5_AMP30.2@6700.4,1754 6700.4,1785.22 ; R5_AMP30.2@6701.78,1754 6712,1743.78 v1(6712,1700) ; R7_AMP30.2@6718,1785.22 6700.4,1785.22 ; R8_AMP1.2@1402.69,1849.91 1411.84,1840.76 ; R8_AMP1.2@1402.69,1849.91 1402,1850.6 R8_AMP1.2@1402.69,1849.91 ; R8_AMP1.2@1402.69,1849.91 1411.84,1840.76 ; 1411.84,1840.76 1411.84,1791 1414.4,1788.44 1414.4,1784.22 ; R8_AMP2.2@1585.69,1849.91 1594.84,1840.76 ; R8_AMP2.2@1585.69,1849.91 1594.84,1840.76 ; R8_AMP2.2@1585.69,1849.91 1585,1850.6 R8_AMP2.2@1585.69,1849.91 ; 1594.84,1840.76 1594.84,1791 1597.4,1788.44 1597.4,1784.22 ; R8_AMP3.2@1768.69,1849.91 1777.84,1840.76 ; R8_AMP3.2@1768.69,1849.91 1768,1850.6 R8_AMP3.2@1768.69,1849.91 ; R8_AMP3.2@1768.69,1849.91 1777.84,1840.76 ; 1777.84,1840.76 1777.84,1791 1780.4,1788.44 1780.4,1784.22 ; R8_AMP4.2@1952.69,1849.91 1961.84,1840.76 ; R8_AMP4.2@1952.69,1849.91 1961.84,1840.76 ; R8_AMP4.2@1952.69,1849.91 1952,1850.6 R8_AMP4.2@1952.69,1849.91 ; 1961.84,1840.76 1961.84,1791 1964.4,1788.44 1964.4,1784.22 ; R8_AMP5.2@2135.69,1849.91 2144.84,1840.76 ; R8_AMP5.2@2135.69,1849.91 2144.84,1840.76 ; R8_AMP5.2@2135.69,1849.91 2135,1850.6 R8_AMP5.2@2135.69,1849.91 ; 2144.84,1840.76 2144.84,1791 2147.4,1788.44 2147.4,1784.22 ; R8_AMP6.2@2317.69,1849.91 2326.84,1840.76 ; R8_AMP6.2@2317.69,1849.91 2326.84,1840.76 ; R8_AMP6.2@2317.69,1849.91 2317,1850.6 R8_AMP6.2@2317.69,1849.91 ; 2326.84,1840.76 2326.84,1791 2329.4,1788.44 2329.4,1784.22 ; R8_AMP7.2@2499.69,1849.91 2508.84,1840.76 ; R8_AMP7.2@2499.69,1849.91 2499,1850.6 R8_AMP7.2@2499.69,1849.91 ; R8_AMP7.2@2499.69,1849.91 2508.84,1840.76 ; 2508.84,1840.76 2508.84,1791 2511.4,1788.44 2511.4,1784.22 ; R8_AMP8.2@2680.69,1849.91 2689.84,1840.76 ; R8_AMP8.2@2680.69,1849.91 2689.84,1840.76 ; R8_AMP8.2@2680.69,1849.91 2680,1850.6 R8_AMP8.2@2680.69,1849.91 ; 2689.84,1840.76 2689.84,1791 2692.4,1788.44 2692.4,1784.22 ; R8_AMP9.2@2861.69,1849.91 2870.84,1840.76 ; R8_AMP9.2@2861.69,1849.91 2861,1850.6 R8_AMP9.2@2861.69,1849.91 ; R8_AMP9.2@2861.69,1849.91 2870.84,1840.76 ; 2870.84,1840.76 2870.84,1791 2873.4,1788.44 2873.4,1784.22 ; R8_AMP10.2@3042.69,1849.91 3051.84,1840.76 ; R8_AMP10.2@3042.69,1849.91 3051.84,1840.76 ; R8_AMP10.2@3042.69,1849.91 3042,1850.6 R8_AMP10.2@3042.69,1849.91 ; 3051.84,1840.76 3051.84,1791 3054.4,1788.44 3054.4,1784.22 ; R8_AMP11.2@3225.69,1849.91 3234.84,1840.76 ; R8_AMP11.2@3225.69,1849.91 3225,1850.6 R8_AMP11.2@3225.69,1849.91 ; R8_AMP11.2@3225.69,1849.91 3234.84,1840.76 ; 3234.84,1840.76 3234.84,1791 3237.4,1788.44 3237.4,1784.22 ; R8_AMP12.2@3406.69,1849.91 3415.84,1840.76 ; R8_AMP12.2@3406.69,1849.91 3415.84,1840.76 ; R8_AMP12.2@3406.69,1849.91 3406,1850.6 R8_AMP12.2@3406.69,1849.91 ; 3415.84,1840.76 3415.84,1791 3418.4,1788.44 3418.4,1784.22 ; R8_AMP13.2@3588.69,1849.91 3597.84,1840.76 ; R8_AMP13.2@3588.69,1849.91 3588,1850.6 R8_AMP13.2@3588.69,1849.91 ; R8_AMP13.2@3588.69,1849.91 3597.84,1840.76 ; 3597.84,1840.76 3597.84,1791 3600.4,1788.44 3600.4,1784.22 ; R8_AMP14.2@3770.69,1849.91 3779.84,1840.76 ; R8_AMP14.2@3770.69,1849.91 3779.84,1840.76 ; R8_AMP14.2@3770.69,1849.91 3770,1850.6 R8_AMP14.2@3770.69,1849.91 ; 3779.84,1840.76 3779.84,1791 3782.4,1788.44 3782.4,1784.22 ; R8_AMP15.2@3952.69,1849.91 3961.84,1840.76 ; R8_AMP15.2@3952.69,1849.91 3952,1850.6 R8_AMP15.2@3952.69,1849.91 ; R8_AMP15.2@3952.69,1849.91 3961.84,1840.76 ; 3961.84,1840.76 3961.84,1791 3964.4,1788.44 3964.4,1784.22 ; R8_AMP16.2@4136.69,1849.91 4145.84,1840.76 ; R8_AMP16.2@4136.69,1849.91 4136,1850.6 R8_AMP16.2@4136.69,1849.91 ; R8_AMP16.2@4136.69,1849.91 4145.84,1840.76 ; 4145.84,1840.76 4145.84,1791 4148.4,1788.44 4148.4,1784.22 ; R8_AMP17.2@4319.69,1849.91 4328.84,1840.76 ; R8_AMP17.2@4319.69,1849.91 4328.84,1840.76 ; R8_AMP17.2@4319.69,1849.91 4319,1850.6 R8_AMP17.2@4319.69,1849.91 ; 4328.84,1840.76 4328.84,1791 4331.4,1788.44 4331.4,1784.22 ; R8_AMP18.2@4501.69,1849.91 4510.84,1840.76 ; R8_AMP18.2@4501.69,1849.91 4510.84,1840.76 ; R8_AMP18.2@4501.69,1849.91 4501,1850.6 R8_AMP18.2@4501.69,1849.91 ; 4510.84,1840.76 4510.84,1791 4513.4,1788.44 4513.4,1784.22 ; R8_AMP19.2@4683.69,1849.91 4692.84,1840.76 ; R8_AMP19.2@4683.69,1849.91 4692.84,1840.76 ; R8_AMP19.2@4683.69,1849.91 4683,1850.6 R8_AMP19.2@4683.69,1849.91 ; 4692.84,1840.76 4692.84,1791 4695.4,1788.44 4695.4,1784.22 ; R8_AMP20.2@4866.69,1849.91 4875.84,1840.76 ; R8_AMP20.2@4866.69,1849.91 4875.84,1840.76 ; R8_AMP20.2@4866.69,1849.91 4866,1850.6 R8_AMP20.2@4866.69,1849.91 ; 4875.84,1840.76 4875.84,1791 4878.4,1788.44 4878.4,1784.22 ; R8_AMP21.2@5049,1850.7 R8_AMP21.2@5049.69,1850.01 ; R8_AMP21.2@5049,1850.7 R8_AMP21.2@5049.69,1850.01 ; R8_AMP21.2@5049,1850.7 R8_AMP21.2@5049.69,1850.01 ; R8_AMP21.2@5049.69,1850.01 5058.84,1840.86 ; R8_AMP21.2@5049.69,1850.01 5058.84,1840.86 ; R8_AMP21.2@5049.69,1850.01 5058.84,1840.86 ; 5058.84,1840.86 5058.84,1791.1 5061.4,1788.54 5061.4,1784.32 ; R8_AMP22.2@5231,1850.7 R8_AMP22.2@5231.69,1850.01 ; R8_AMP22.2@5231,1850.7 R8_AMP22.2@5231.69,1850.01 ; R8_AMP22.2@5231,1850.7 R8_AMP22.2@5231.69,1850.01 ; R8_AMP22.2@5231.69,1850.01 5240.84,1840.86 ; R8_AMP22.2@5231.69,1850.01 5240.84,1840.86 ; R8_AMP22.2@5231.69,1850.01 5240.84,1840.86 ; 5240.84,1840.86 5240.84,1791.1 5243.4,1788.54 5243.4,1784.32 ; R8_AMP23.2@5413,1850.7 R8_AMP23.2@5413.69,1850.01 ; R8_AMP23.2@5413,1850.7 R8_AMP23.2@5413.69,1850.01 ; R8_AMP23.2@5413,1850.7 R8_AMP23.2@5413.69,1850.01 ; R8_AMP23.2@5413.69,1850.01 5422.84,1840.86 ; R8_AMP23.2@5413.69,1850.01 5422.84,1840.86 ; R8_AMP23.2@5413.69,1850.01 5422.84,1840.86 ; 5422.84,1840.86 5422.84,1791.1 5425.4,1788.54 5425.4,1784.32 ; R8_AMP24.2@5595,1850.7 R8_AMP24.2@5595.69,1850.01 ; R8_AMP24.2@5595,1850.7 R8_AMP24.2@5595.69,1850.01 ; R8_AMP24.2@5595,1850.7 R8_AMP24.2@5595.69,1850.01 ; R8_AMP24.2@5595.69,1850.01 5604.84,1840.86 ; R8_AMP24.2@5595.69,1850.01 5604.84,1840.86 ; R8_AMP24.2@5595.69,1850.01 5604.84,1840.86 ; 5604.84,1840.86 5604.84,1791.1 5607.4,1788.54 5607.4,1784.32 ; R8_AMP25.2@5777,1850.7 R8_AMP25.2@5777.69,1850.01 ; R8_AMP25.2@5777,1850.7 R8_AMP25.2@5777.69,1850.01 ; R8_AMP25.2@5777,1850.7 R8_AMP25.2@5777.69,1850.01 ; R8_AMP25.2@5777.69,1850.01 5786.84,1840.86 ; R8_AMP25.2@5777.69,1850.01 5786.84,1840.86 ; R8_AMP25.2@5777.69,1850.01 5786.84,1840.86 ; 5786.84,1840.86 5786.84,1791.1 5789.4,1788.54 5789.4,1784.32 ; R8_AMP26.2@5960,1851.17 R8_AMP26.2@5960.69,1850.48 ; R8_AMP26.2@5960,1851.17 R8_AMP26.2@5960.69,1850.48 ; R8_AMP26.2@5960,1851.17 R8_AMP26.2@5960.69,1850.48 ; R8_AMP26.2@5960.69,1850.48 5969.84,1841.33 ; R8_AMP26.2@5960.69,1850.48 5969.84,1841.33 ; R8_AMP26.2@5960.69,1850.48 5969.84,1841.33 ; 5969.84,1841.33 5969.84,1791.57 5972.4,1789.01 5972.4,1784.79 ; R8_AMP27.2@6142,1851.17 R8_AMP27.2@6142.69,1850.48 ; R8_AMP27.2@6142,1851.17 R8_AMP27.2@6142.69,1850.48 ; R8_AMP27.2@6142,1851.17 R8_AMP27.2@6142.69,1850.48 ; R8_AMP27.2@6142.69,1850.48 6151.84,1841.33 ; R8_AMP27.2@6142.69,1850.48 6151.84,1841.33 ; R8_AMP27.2@6142.69,1850.48 6151.84,1841.33 ; 6151.84,1841.33 6151.84,1791.57 6154.4,1789.01 6154.4,1784.79 ; R8_AMP28.2@6324,1851.17 R8_AMP28.2@6324.69,1850.48 ; R8_AMP28.2@6324,1851.17 R8_AMP28.2@6324.69,1850.48 ; R8_AMP28.2@6324,1851.17 R8_AMP28.2@6324.69,1850.48 ; R8_AMP28.2@6324.69,1850.48 6333.84,1841.33 ; R8_AMP28.2@6324.69,1850.48 6333.84,1841.33 ; R8_AMP28.2@6324.69,1850.48 6333.84,1841.33 ; 6333.84,1841.33 6333.84,1791.57 6336.4,1789.01 6336.4,1784.79 ; R8_AMP29.2@6506,1851.17 R8_AMP29.2@6506.69,1850.48 ; R8_AMP29.2@6506,1851.17 R8_AMP29.2@6506.69,1850.48 ; R8_AMP29.2@6506,1851.17 R8_AMP29.2@6506.69,1850.48 ; R8_AMP29.2@6506.69,1850.48 6515.84,1841.33 ; R8_AMP29.2@6506.69,1850.48 6515.84,1841.33 ; 6515.84,1841.33 6515.84,1791.57 6518.4,1789.01 6518.4,1784.79 ; R8_AMP30.2@6688,1851.6 R8_AMP30.2@6688.69,1850.91 ; R8_AMP30.2@6688,1851.6 R8_AMP30.2@6688.69,1850.91 ; R8_AMP30.2@6688,1851.6 R8_AMP30.2@6688.69,1850.91 ; R8_AMP30.2@6688.69,1850.91 6697.84,1841.76 ; R8_AMP30.2@6688.69,1850.91 6697.84,1841.76 ; R8_AMP30.2@6688.69,1850.91 6697.84,1841.76 ; 6697.84,1841.76 6697.84,1792 6700.4,1789.44 6700.4,1785.22
  other v1: 2067,2556 2982,2556 3890,2556 4801,2556 5714,2556.1 6625,2556.57 1796,2568 2711,2568 3619,2568 4530,2568 5443,2568.1 6354,2568.57
pads on no net: D1.3 M1_SUMMER1.2 M1_SUMMER2.2 M1_SUMMER3.2 M1_SUMMER4.2 M1_SUMMER5.2 M1_SUMMER6.2 P1.33 P1.34 P1.A2 P1.A4 P1.A5 P1.A7 P1.A8 P1.A9 P1.A10 P1.A12 P1.A13 P1.A14 P1.A15 P1.A17 P1.A18 P1.A19 P1.A20 P1.A22 P1.A23 P1.A24 P1.A25 P1.A27 P1.A28 P1.C31 P1.C32

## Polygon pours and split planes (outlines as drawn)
BASE2 on BASES "+5V" (solid, pour order 1001): 1004,3398 1247,3641 6736,3641 7001,3376 7001,1566 6883,1448 1009.24,1448 1006,1451 1004,1501
BASE1 on BASES "+5V" (solid, pour order 1000): 1621,3486 6168,3484 6168,2345 6012,2189 1751,2189 1324,2192 1327,2613 1476,2762 1476,2893 1622,3039 1622,3423
GND on GND (split plane): 6979.61,1245.32 6805.5,1020.39 1194.62,1020.39 1020.39,1245.47 1020.39,3619.61 6979.61,3619.61
VCC on VCC (split plane): 6979.61,1245.32 6805.5,1020.39 1194.62,1020.39 1020.39,1245.47 1020.39,3619.61 6979.61,3619.61
GND on GND (Plane3) (split plane): 6979.61,1245.32 6805.5,1020.39 1194.62,1020.39 1020.39,1245.47 1020.39,3619.61 6979.61,3619.61

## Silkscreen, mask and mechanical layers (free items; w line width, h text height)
Top Overlay:
  circle w10: c6821.13,1368 r18.87
  circle w10: c6888.13,1369 r18.87
  circle w10: c6805.13,1634 r18.87
  circle w10: c6915.13,1693 r18.87
  circle w10: c6792.13,1744 r18.87
  circle w10: c6891.13,1922 r18.87
  circle w10: c6772.13,2036 r18.87
  circle w10: c6839.13,2111 r18.87
  circle w10: c6898.13,2126 r18.87
  circle w10: c6882.13,2327 r18.87
  circle w10: c1194.13,2332 r18.87
  circle w10: c1210.13,2131 r18.87
  circle w10: c1151.13,2116 r18.87
  circle w10: c1084.13,2041 r18.87
  circle w10: c1203.13,1927 r18.87
  circle w10: c1104.13,1749 r18.87
  circle w10: c1227.13,1698 r18.87
  circle w10: c1117.13,1639 r18.87
  circle w10: c1200.13,1374 r18.87
  circle w10: c1133.13,1373 r18.87
  lines w7: 1247,2409 1247,2809 ; 1450.5,1075 1450.5,2384 ; 1542.21,2584.79 1554,2573 ; 1633,1075 1633,2384 ; 1815.5,1075 1815.5,2384 ; 1998,1075 1998,2384 ; 2162,2409 2162,2809 ; 2180.5,1075 2180.5,2384 ; 2363,1075 2363,2384 ; 2457.21,2585.79 2469,2574 ; 2545.5,1075 2545.5,2384 ; 2728,1075 2728,2384 ; 2910.5,1075 2910.5,2384 ; 3072,2409 3072,2809 ; 3093,1075 3093,2384 ; 3275.5,1075 3275.5,2384 ; 3366.65,2582.43 3378.44,2570.64 ; 3458,1075 3458,2384 ; 3640.5,1075 3640.5,2384 ; 3823,1075 3823,2384 ; 3980,2410 3980,2810 ; 4005.5,1075 4005.5,2384 ; 4188,1075 4188,2384 ; 4276.21,2585.79 4288,2574 ; 4370.5,1075 4370.5,2384 ; 4553,1075 4553,2384 ; 4735.5,1075 4735.5,2384 ; 4892,2411 4892,2811 ; 4918,1075 4918,2384 ; 5100.5,1075 5100.5,2384 ; 5190.21,2584.79 5202,2573 ; 5283,1075 5283,2384 ; 5465.5,1075 5465.5,2384 ; 5648,1075 5648,2384 ; 5805,2409 5805,2809 ; 5830.5,1075 5830.5,2384 ; 6013,1075 6013,2384 ; 6101.65,2583 6113.44,2571.21 ; 6195.5,1075 6195.5,2384 ; 6378,1075 6378,2384 ; 6560.5,1075 6560.5,2384 ; 6737,2409 6737,2809 ; 6743,1075 6743,2384 ; 1268,1075 1268,2384 1268,1075
  lines w10: 1229,1087 1229,1233 1077,1233 1077,1087 1231,1087 ; 6917,1082 6917,1228 6765,1228 6765,1082 6919,1082 ; 1082,2167 1219,2167 1219,2297 1082,2297 1082,2167 ; 1089,1821 1171,1821 1171,1902 1089,1902 1089,1821 ; 1092,1413 1092,1543 1229,1543 1229,1413 1092,1413 ; 1122,1973 1122,2054 1204,2054 1204,1973 1122,1973 ; 6770,2162 6770,2292 6907,2292 6907,2162 6770,2162 ; 6777,1816 6777,1897 6859,1897 6859,1816 6777,1816 ; 6780,1408 6917,1408 6917,1538 6780,1538 6780,1408 ; 6810,1968 6892,1968 6892,2049 6810,2049 6810,1968
  text "SiPM Amplifier Board" at 6141,3533 h40
  text "Version 1.0" at 6139,3478 h30
  text "Designed by UCONN Jones Lab" at 6139,3431 h30
  text "For USDOE GlueX Experiment" at 6141,3376 h30
  text "Thomas Jefferson Nat'l Lab" at 6141,3326 h30
  text "Newport News, VA" at 6141,3275 h30
  text "SUMMER1" at 1281,2766 h20
  text "SUMMER2" at 2196,2766 h20
  text "SUMMER3" at 3111,2766 h20
  text "SUMMER4" at 4026,2766 h20
  text "SUMMER5" at 4941,2766 h20
  text "SUMMER6" at 5856,2766 h20
  text "AMP1" at 1302,2364 h20
  text "AMP2" at 1485,2364 h20
  text "AMP3" at 1668,2364 h20
  text "AMP4" at 1851,2364 h20
  text "AMP5" at 2034,2364 h20
  text "AMP6" at 2217,2364 h20
  text "AMP7" at 2400,2364 h20
  text "AMP8" at 2583,2364 h20
  text "AMP9" at 2766,2364 h20
  text "AMP10" at 2949,2364 h20
  text "AMP11" at 3132,2364 h20
  text "AMP12" at 3315,2364 h20
  text "AMP13" at 3498,2364 h20
  text "AMP14" at 3681,2364 h20
  text "AMP15" at 3864,2364 h20
  text "AMP16" at 4047,2364 h20
  text "AMP17" at 4230,2364 h20
  text "AMP18" at 4413,2364 h20
  text "AMP19" at 4596,2364 h20
  text "AMP20" at 4779,2364 h20
  text "AMP21" at 4962,2364 h20
  text "AMP22" at 5145,2364 h20
  text "AMP23" at 5328,2364 h20
  text "AMP24" at 5511,2364 h20
  text "AMP25" at 5694,2364 h20
  text "AMP26" at 5877,2364 h20
  text "AMP27" at 6060,2364 h20
  text "AMP28" at 6243,2364 h20
  text "AMP29" at 6426,2364 h20
  text "AMP30" at 6609,2364 h20
  text "AMP#" at 1116,2362 h20
  text "AMP#" at 6804,2357 h20
  text "Q1" at 1135,2217 h30
  text "Q1" at 6823,2212 h30
  text "Q3" at 1139,1999 h30
  text "Q3" at 6827,1994 h30
  text "C6" at 1246,1868 h20 r90
  text "C6" at 6934,1863 h20 r90
  text "R8" at 1214,1851 h20 r90
  text "Q2" at 1106,1847 h30
  text "R8" at 6902,1846 h20 r90
  text "Q2" at 6794,1842 h30
  text "C5" at 1205,1783 h20 r90
  text "R7" at 1242,1783 h20 r90
  text "C5" at 6893,1778 h20 r90
  text "R7" at 6930,1778 h20 r90
  text "R5" at 1192,1742 h20
  text "R5" at 6880,1737 h20
  text "R4" at 1161,1709 h20
  text "R4" at 6849,1704 h20
  text "R3" at 1117,1681 h20 r90
  text "R3" at 6805,1676 h20 r90
  text "R2" at 1151,1674 h20
  text "R2" at 6839,1669 h20
  text "R20" at 1197,1643 h20
  text "R20" at 6885,1638 h20
  text "CBi" at 1093,1561 h20 r90
  text "RBi" at 1133,1561 h20 r90
  text "C4" at 1173,1561 h20 r90
  text "R6" at 1213,1561 h20 r90
  text "C3" at 1248,1559 h20 r90
  text "CBi" at 6781,1556 h20 r90
  text "RBi" at 6821,1556 h20 r90
  text "C4" at 6861,1556 h20 r90
  text "R6" at 6901,1556 h20 r90
  text "C3" at 6936,1554 h20 r90
  text "Q0" at 1136,1459 h30
  text "Q0" at 6824,1454 h30
  text "C2" at 1099,1285 h20 r90
  text "R1" at 1139,1285 h20 r90
  text "C1" at 1179,1285 h20 r90
  text "R18" at 1219,1285 h20 r90
  text "C2" at 6787,1280 h20 r90
  text "R1" at 6827,1280 h20 r90
  text "C1" at 6867,1280 h20 r90
  text "R18" at 6907,1280 h20 r90
  text "R19" at 1091,1253 h20
  text "R19" at 6779,1248 h20
  text "SiPM" at 1094,1150 h30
